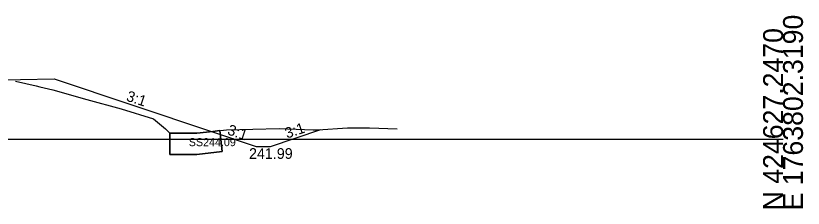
# Model space of a CAD drawing. Extents: x -26 to 3203, y -11010 to 4024.
# Drawn here: x 2192.1 to 2302.8, y 2492.9 to 2520 of the extents above; entities that cross this region are included whole.
import ezdxf

# ---------------------------------------------------------------- set-up
doc = ezdxf.new("R2010")
doc.units = 0
for name, color, linetype in [('Exist Cross Section Cell', 7, 'Continuous'), ('Exist XS Ground Line', 7, 'Continuous'), ('Prop CMT Ditch DDE', 7, 'Continuous'), ('Prop CMT Slope Grass', 7, 'Continuous'), ('Prop CMT Undercut', 7, 'Continuous'), ('Prop CMT Undercut Boundary', 7, 'Continuous'), ('Prop XS Ditch Standard Text', 7, 'Continuous'), ('Prop XS Side Slope Text', 7, 'Continuous'), ('Prop XS SS Elevation Text', 7, 'Continuous'), ('Scratch_Level_0', 7, 'Continuous')]:
    doc.layers.add(name, color=color, linetype=linetype)

msp = doc.modelspace()

# ---------------------------------------------------------------- linework, layer by layer
at = {"layer": 'Exist Cross Section Cell'}
msp.add_line((2150, 2502.62), (2300, 2502.62), dxfattribs=at)
at = {"layer": 'Exist XS Ground Line'}
msp.add_lwpolyline([(2192.07, 2510.76), (2195, 2510.1), (2195.51, 2509.97), (2197.31, 2509.57), (2202.09, 2508.2), (2206.91, 2506.88), (2211.47, 2505.48), (2213.16, 2504.06), (2213.77, 2503.47), (2217.56, 2503.47), (2221.74, 2503.94), (2229.17, 2504.13), (2232.7, 2503.96), (2233.95, 2503.95), (2234.59, 2503.94), (2238.75, 2504.2), (2240.51, 2504.21), (2241.84, 2504.21), (2245.75, 2504.09)], dxfattribs=at)
msp.add_lwpolyline([(2192.07, 2510.76), (2195, 2510.1), (2195.51, 2509.97), (2197.31, 2509.57), (2202.09, 2508.2), (2206.91, 2506.88), (2211.47, 2505.48), (2213.16, 2504.06), (2213.77, 2503.47), (2217.56, 2503.47), (2221.74, 2503.94), (2229.17, 2504.13), (2232.7, 2503.96), (2233.95, 2503.95), (2234.59, 2503.94), (2238.75, 2504.2), (2240.51, 2504.21), (2241.84, 2504.21), (2245.75, 2504.09)], dxfattribs=at)
msp.add_lwpolyline([(2192.07, 2510.76), (2195, 2510.1), (2195.51, 2509.97), (2197.31, 2509.57), (2202.09, 2508.2), (2206.91, 2506.88), (2211.47, 2505.48), (2213.16, 2504.06), (2213.77, 2503.47), (2217.56, 2503.47), (2221.74, 2503.94), (2229.17, 2504.13), (2232.7, 2503.96), (2233.95, 2503.95), (2234.59, 2503.94), (2238.75, 2504.2), (2240.51, 2504.21), (2241.84, 2504.21), (2245.75, 2504.09)], dxfattribs=at)
msp.add_lwpolyline([(2192.07, 2510.76), (2195, 2510.1), (2195.51, 2509.97), (2197.31, 2509.57), (2202.09, 2508.2), (2206.91, 2506.88), (2211.47, 2505.48), (2213.16, 2504.06), (2213.77, 2503.47), (2217.56, 2503.47), (2221.74, 2503.94), (2229.17, 2504.13), (2232.7, 2503.96), (2233.95, 2503.95), (2234.59, 2503.94), (2238.75, 2504.2), (2240.51, 2504.21), (2241.84, 2504.21), (2245.75, 2504.09)], dxfattribs=at)
msp.add_lwpolyline([(2192.07, 2510.76), (2195, 2510.1), (2195.51, 2509.97), (2197.31, 2509.57), (2202.09, 2508.2), (2206.91, 2506.88), (2211.47, 2505.48), (2213.16, 2504.06), (2213.77, 2503.47), (2217.56, 2503.47), (2221.74, 2503.94), (2229.17, 2504.13), (2232.7, 2503.96), (2233.95, 2503.95), (2234.59, 2503.94), (2238.75, 2504.2), (2240.51, 2504.21), (2241.84, 2504.21), (2245.75, 2504.09)], dxfattribs=at)
at = {"layer": 'Prop CMT Ditch DDE'}
for points in [[(2219.65, 2503.71), (2225.93, 2501.61), (2227.93, 2501.61), (2235.01, 2503.97)], [(2219.65, 2503.71), (2219.65, 2503.71)]]:
    msp.add_lwpolyline(points, dxfattribs=at)
at = {"layer": 'Prop CMT Slope Grass'}
msp.add_lwpolyline([(2188, 2510.9), (2197.5, 2511.09), (2219.65, 2503.71)], dxfattribs=at)
at = {"layer": 'Prop CMT Undercut'}
msp.add_lwpolyline([(2217.56, 2503.47), (2213.77, 2503.47), (2213.77, 2500.47), (2217.56, 2500.47), (2221.14, 2500.87), (2220.81, 2503.84), (2219.82, 2503.72), (2217.56, 2503.47)], dxfattribs=at)
at = {"layer": 'Prop CMT Undercut Boundary'}
msp.add_lwpolyline([(2219.82, 2503.72), (2220.81, 2503.84), (2221.14, 2500.87), (2217.56, 2500.47), (2213.77, 2500.47), (2213.77, 2503.47), (2217.56, 2503.47)], close=True, dxfattribs=at)

# ---------------------------------------------------------------- texts
at = {"layer": 'Exist Cross Section Cell'}
for s, p in [('E 1763802.3190', (2302.8, 2492.62)), ('N 424627.2470', (2300, 2492.62))]:
    msp.add_text(s, height=2.8, rotation=90, dxfattribs=at).set_placement(p)
at = {"layer": 'Prop XS Ditch Standard Text'}
msp.add_text('241.99', height=1.5, dxfattribs=at).set_placement((2224.91, 2499.86))
at = {"layer": 'Prop XS Side Slope Text'}
for rotation, p in [(341.5651, (2207.54, 2508.06)), (18.4349, (2230.25, 2502.7)), (341.5651, (2221.76, 2503.32))]:
    msp.add_text('3:1', height=1.5, rotation=rotation, dxfattribs=at).set_placement(p)
at = {"layer": 'Prop XS SS Elevation Text'}
msp.add_text('SS244.09', height=1.125, dxfattribs=at).set_placement((2216.44, 2501.64))
at = {"layer": 'Scratch_Level_0'}
for s, p in [('RT_CSLP_Pnt', (2197.4, 2511.08)), ('RT_DD_Boundary In', (2219.49, 2503.7)), ('RT_Slope_Fill', (2219.55, 2503.7)), ('RT_DD_Boundary Out', (2234.84, 2503.96)), ('Exterior Boundary', (2234.85, 2503.96)), ('RT_DD_Base In', (2225.82, 2501.6)), ('RT_DD_Base Out', (2227.8, 2501.6))]:
    msp.add_text(s, height=0.02, dxfattribs=at).set_placement(p)

doc.saveas('drawing.dxf')
